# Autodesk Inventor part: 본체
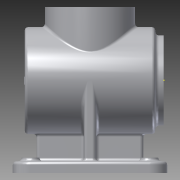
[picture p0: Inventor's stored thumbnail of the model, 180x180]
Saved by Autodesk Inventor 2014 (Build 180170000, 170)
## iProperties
Created: 2015-07
Part Number: 본체
Material: Aluminum 6061
Document SubType Name: Modeling
Designer: user
Density: 2.71 g/cm^3
Appearance: Aluminum - Flat
Mass: 1277.62 g
Surface Area: 1267.64 cm^2
Volume: 471.448 cm^3
Author: user
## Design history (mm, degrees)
sketch "Sketch1"
  geometry: L1 (0, 0)-(-117, 0); L2 (0, 38)-(-7, 38); L3 (-7, 38)-(-7, 45); L4 (-7, 45)-(-117, 45); L5 (-117, 0)-(-117, 45); L6 (0, 27)-(0, 38); L7 (0, 27)-(-14, 27); L8 (-14, 27)-(-14, 40); L9 (-14, 40)-(-110, 40); L10 (-110, 40)-(-110, 0)
  constraints: 20 end point, 5 perpendicular, 4 parallel, 1 horizontal, 1 point on line
  dimensions: "d0" = 117 distance of L1.start L1.end; "d1" = 76 diameter of L2 L1; "d2" = 90 diameter of L4 L1; "d3" = 7 distance of L2.start L2.end; "d4" = 54 diameter of L7 L1; "d5" = 14 distance between parallel lines of L8 L6; "d6" = 80 diameter of L9 L1; "d7" = 7 distance between parallel lines of L5 L10; "d8" = 110 distance between parallel lines of L6 L10
revolve "Revolution1" sketch "Sketch1" stored, may be unused: angle "d9" = 90 deg
workplane "Work Plane1"
sketch "Sketch2"
  geometry: L1 (-3, 65)-(127, 65); L2 (127, 65)-(127, -65); L3 (127, -65)-(-3, -65); L4 (-3, -65)-(-3, 65); L5 (117, 45)-(117, -45) reference; 2 further points
  constraints: 8 end point, 2 parallel, 1 horizontal, 1 horizontal alignment, 1 midpoint, 1 perpendicular
  dimensions: "d11" = 130 distance of L2.end L3.end; "d12" = 130 distance of L1.end L2.end; "d13" = 10 distance between parallel lines of L2 L5
extrude "Extrusion1" join sketch "Sketch2" distance "d14" = 10; taper "d15" = 0 deg
sketch "Sketch3"
  geometry: L1 (127, 65)-(-3, 65) reference; L2 (-3, 65)-(-3, -65) reference; L3 (127, -65)-(127, 65) reference; L4 (107, 5)-(107, -5); L5 (17, -5)-(17, 5); L6 (57, 45)-(67, 45); L7 (67, -45)-(57, -45); L8 (17, 5)-(57, 5); L9 (67, 5)-(107, 5); L10 (67, 45)-(67, 5); L11 (67, -5)-(67, -45); L12 (57, -45)-(57, -5); L13 (57, 5)-(57, 45); L14 (107, -5)-(67, -5); L15 (57, -5)-(17, -5); 7 further points
  constraints: 24 end point, 10 parallel, 4 midpoint, 4 perpendicular, 3 horizontal, 2 horizontal alignment, 2 vertical alignment
  dimensions: "d16" = 90 distance of L4.end L5.start; "d17" = 10 distance of L4.start L4.end; "d18" = 10 distance of L7.start L7.end; "d19" = 90 distance of L6.end L7.start; "d20" = 20 distance between parallel lines of L1 L6; "d21" = 110 distance between parallel lines of L1 L7; "d22" = 60 distance between parallel lines of L1 L8; "d23" = 20 distance between parallel lines of L3 L4; "d24" = 60 distance between parallel lines of L3 L10; "d25" = 110 distance between parallel lines of L3 L5; "d26" = 60 distance from line of point (62, 5) L1; "d27" = 70 distance from line of point (57, 0) L3
extrude "Extrusion2" join sketch "Sketch3" stored distance "d28" = 10; taper "d29" = 0 deg
sketch "Sketch4"
  geometry: L1 (127, 65)-(-3, 65) reference; L2 (-3, 65)-(-3, -65) reference; L3 (127, -65)-(127, 65) reference; 5 further points
  constraints: 2 horizontal alignment
  dimensions: "d30" = 15 distance from line of L3 point (112, 50); "d31" = 100 distance of point (12, 50) point (112, 50); "d32" = 15 distance from line of L1 point (112, 50) (= d30); "d33" = 100 distance of point (112, -50) point (112, 50) (= d31); "d34" = 15 distance from line of point (12, -50) L2; "d35" = 15 distance from line of L3 point (112, -50)
hole "Hole1" sketch "Sketch4" at (12, 50), (112, 50), (12, -50), (112, -50) diameter "d36" = 10; stored, may be unused: countersink angle "d40" = 90 deg, drill point angle "d42" = 118 deg; dims "d37" = 6, "d38" = 4, "d39" = 2, "d41" = 8
sketch "Sketch5"
  geometry: C1 r 5 at (12, -50) reference; C2 r 5 at (12, 50) reference; C3 r 5 at (112, 50) reference; C4 r 5 at (112, -50) reference; C5 r 7.5 at (12, 50); C6 r 7.5 at (112, 50); C7 r 7.5 at (12, -50); C8 r 7.5 at (112, -50); 1 further point
  constraints: 4 centre point, 3 equal radius
  dimensions: "d43" = 15 diameter of C5
extrude "Extrusion3" join sketch "Sketch5" distance "d44" = 3; taper "d45" = 0 deg
workplane "Work Plane2"
sketch "Sketch6"
  geometry: L1 (-117, -45)-(-117, 45) reference; C1 r 38 at (-62, 0); 1 further point
  constraints: 1 centre point
  dimensions: "d47" = 76 diameter of C1; "d48" = 55 distance from line of C1.centre L1
extrude "Extrusion4" join sketch "Sketch6" stored distance "d49" = 3; taper "d50" = 0 deg
sketch "Sketch7"
  geometry: C1 r 38 at (0, 0) reference; C2 r 27 at (0, 0); 1 further point
  constraints: 1 centre point, 1 coincident
  dimensions: "d51" = 54 diameter of C2
extrude "Extrusion5" cut sketch "Sketch7" stored distance "d52" = 3; taper "d53" = 0 deg
sketch "Sketch8"
  geometry: C1 r 27 at (0, 0) reference; 2 further points
  dimensions: "d54" = 32 distance of point (32, 0) C1.centre
hole "Hole2" sketch "Sketch8" at (32, 0) diameter "d55" = 3.242; stored, may be unused: countersink angle "d59" = 90 deg, drill point angle "d61" = 118 deg; dims "d56" = 8, "d57" = 12.24, "d58" = 3.58, "d60" = 10
pattern_circular "Circular Pattern1" dims angle "d63" = 360 deg
sketch "Sketch9"
  geometry: C1 r 38 at (0, 0) reference; 1 further point
  dimensions: "d65" = 32 distance of point (32, 0) C1.centre
hole "Hole3" sketch "Sketch9" at (32, 0) diameter "d66" = 3.242; stored, may be unused: countersink angle "d70" = 90 deg, drill point angle "d72" = 118 deg; dims "d67" = 8, "d68" = 12.24, "d69" = 3.58, "d71" = 10
pattern_circular "Circular Pattern2" dims angle "d74" = 360 deg
chamfer "Chamfer1" distance "d76" = 1; stored, may be unused: second distance "d77" = 2, angle "d78" = 45 deg
fillet "Fillet1" dims "d79" = 3
fillet "Fillet2" dims "d80" = 3
fillet "Fillet3" dims "d81" = 3
fillet "Fillet4" dims "d82" = 3
fillet "Fillet5" dims "d83" = 3
fillet "Fillet6" dims "d84" = 3
fillet "Fillet7" dims "d85" = 3
fillet "Fillet8" dims "d86" = 3
fillet "Fillet9" dims "d87" = 3
fillet "Fillet10" dims "d88" = 15
fillet "Fillet11" dims "d89" = 3
sketch "Sketch10"
  geometry: L1 (-3.602, -24.887)-(-3.602, 24.887); L2 (-3.602, 24.887)-(3.602, 24.887); L3 (3.602, 24.887)-(3.602, -24.887); L4 (3.602, -24.887)-(-3.602, -24.887); C1 r 42 at (0, 0) reference; 1 further point
  constraints: 1 coincident, 2 other
emboss "Emboss1" sketch "Sketch10" dims "d0" = 117, "d1" = 76, "d2" = 90, "d3" = 7, "d4" = 54, "d5" = 14, "d6" = 80, "d7" = 7, "d8" = 110, "d90" = 0.5, "d91" = 0
sketch "Sketch11"
  geometry: 1 further point
body "Solid1"
other parameters: "d10" = -78
